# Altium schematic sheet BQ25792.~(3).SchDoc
size A2; Date: Not shown in title block; ApprovedBy: Not shown in title block; CheckedBy: Not shown in title block; Author: Not shown in title block; CompanyName: Not shown in title block; Engineer: Not shown in title block; Organization: Not shown in title block; Address1: Not shown in title block; Address2: Not shown in title block; Address3: Not shown in title block; Address4: Not shown in title block; DocumentNumber: 2; Revision: Use project parameter SCH_Rev; SheetNumber: 2; SheetTotal: 3; PageSetup: Record=PageOptions¦CenterHorizontal=True¦CenterVertical=True¦PrintScale=1.00¦XCorrection=1.00¦YCorrection=1.00¦PrintKind=0¦BorderSize=5000000¦LeftOffset=0¦BottomOffset=0¦Orientation=2¦PaperLength=1000¦PaperWidth=1000¦Scale=100¦PaperSource=15¦PrintQuality=600¦MediaType=1¦DitherType=10¦PaperKind=Letter¦PrintScaleMode=1
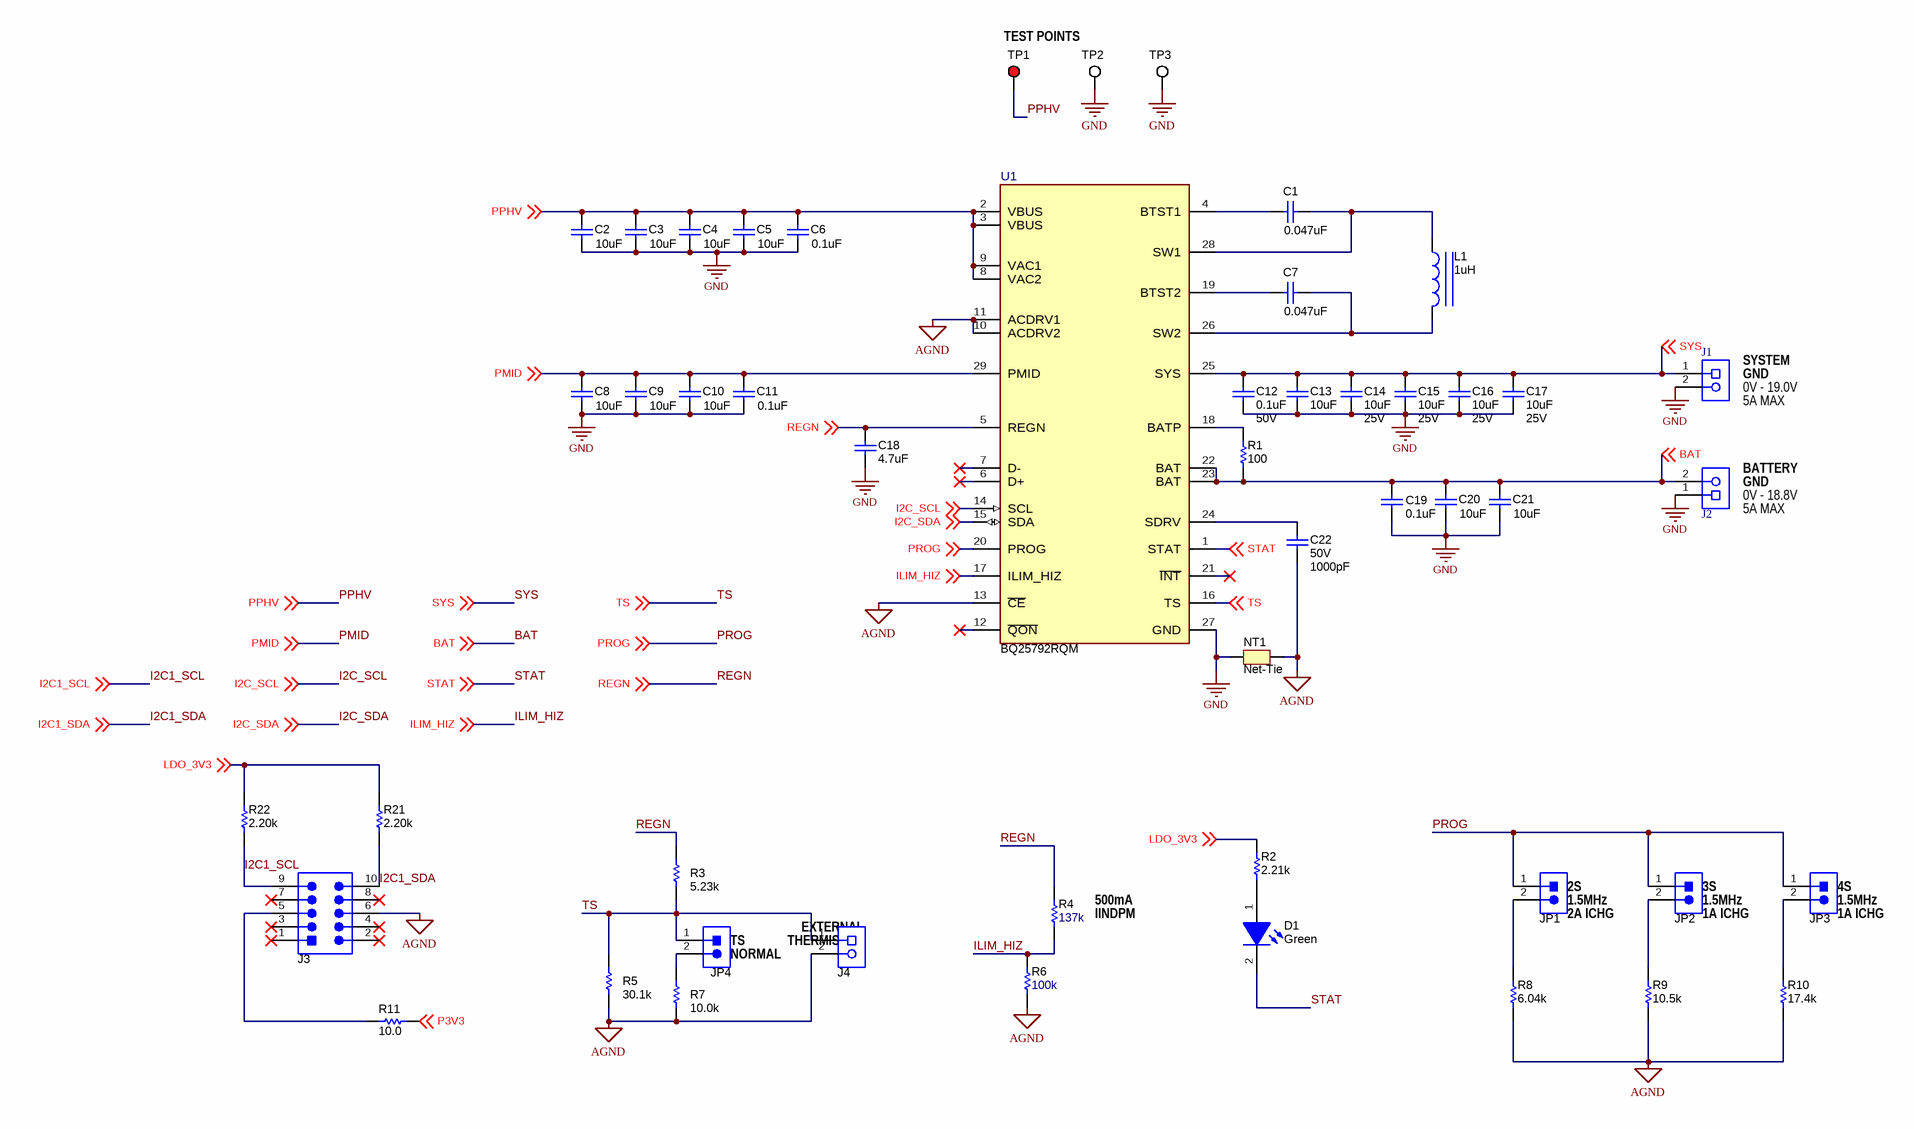
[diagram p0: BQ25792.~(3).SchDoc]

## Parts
C1  ValueDisplayed: 0.047uF  [0402]  (hidden comment: GRM155R71E473KA88D)
C2  ValueDisplayed: 10uF  [0603]  (hidden comment: GRT188R61E106ME13D)
C3  ValueDisplayed: 10uF  [0603]  (hidden comment: GRT188R61E106ME13D)
C4  ValueDisplayed: 10uF  [0603]  (hidden comment: GRT188R61E106ME13D)
C5  ValueDisplayed: 10uF  [0603]  (hidden comment: GRT188R61E106ME13D)
C6  ValueDisplayed: 0.1uF  [0402]  (hidden comment: C1005X7R1H104K050BE)
C7  ValueDisplayed: 0.047uF  [0402]  (hidden comment: GRM155R71E473KA88D)
C8  ValueDisplayed: 10uF  [0603]  (hidden comment: GRT188R61E106ME13D)
C9  ValueDisplayed: 10uF  [0603]  (hidden comment: GRT188R61E106ME13D)
C10  ValueDisplayed: 10uF  [0603]  (hidden comment: GRT188R61E106ME13D)
C11  ValueDisplayed: 0.1uF  [0402]  (hidden comment: C1005X7R1H104K050BE)
C12  ValueDisplayed: 0.1uF  VDC_V: 50V  [0402]  (hidden comment: C1005X7R1H104K050BE)
C13  ValueDisplayed: 10uF  [0805_HV]  (hidden comment: C2012X5R1E106K125AB)
C14  ValueDisplayed: 10uF  VDC_V: 25V  [0805_HV]  (hidden comment: C2012X5R1E106K125AB)
C15  ValueDisplayed: 10uF  VDC_V: 25V  [0805_HV]  (hidden comment: C2012X5R1E106K125AB)
C16  ValueDisplayed: 10uF  VDC_V: 25V  [0805_HV]  (hidden comment: C2012X5R1E106K125AB)
C17  ValueDisplayed: 10uF  VDC_V: 25V  [0805_HV]  (hidden comment: C2012X5R1E106K125AB)
C18  ValueDisplayed: 4.7uF  [0603]  (hidden comment: GRM188R61C475KAAJ)
C19  ValueDisplayed: 0.1uF  [0402L]  (hidden comment: C1005X7R1H104K050BE)
C20  ValueDisplayed: 10uF  [0603]  (hidden comment: GRT188R61E106ME13D)
C21  ValueDisplayed: 10uF  [0603]  (hidden comment: GRT188R61E106ME13D)
C22  VDC_V: 50V  ValueDisplayed: 1000pF  [0402]  (hidden comment: C0402C102K5RACTU)
D1  value Green  [LED_LTST-C190]  (hidden comment: LTST-C190GKT)
J1  ED120/2DS  [On-Shore_ED120_2DS]  (value not drawn)
J2  ED120/2DS  [On-Shore_ED120_2DS]  (value not drawn)
J3  N2510-6002-RB  [CONN_2510-6002]  (value not drawn)
J4  0393570002  [MOLEX_39357-0002]  (value not drawn)
JP1  Header_2x1  [CONN_PEC02SAAN]  (value not drawn)
JP2  Header_2x1  [CONN_PEC02SAAN]  (value not drawn)
JP3  Header_2x1  [CONN_PEC02SAAN]  (value not drawn)
JP4  Header_2x1  [CONN_PEC02SAAN]  (value not drawn)
L1  ValueDisplayed: 1uH  [IHLP-2020BZ]  (hidden comment: IHLP2020BZER1R0M11)
NT1  Net-Tie  [Net-Tie_20milWide_60milLong]  (net tie, no BOM)
R1  ValueDisplayed: 100  [0603]  (hidden comment: RC0603FR-07100RL)
R2  value 2.21k  [0402]  (hidden comment: CRCW04022K21FKED)
R3  value 5.23k  [0402]  (hidden comment: Resistor)
R4  ValueDisplayed: 137k  [0603]  (hidden comment: RC0603FR-07137KL)
R5  value 30.1k  [0402]  (hidden comment: Resistor)
R6  ValueDisplayed: 100k  [0603]  (hidden comment: RC0603FR-07100KL)
R7  value 10.0k  [0402]  (hidden comment: Resistor)
R8  ValueDisplayed: 6.04k  [0603]  (hidden comment: RC0603FR-076K04L)
R9  ValueDisplayed: 10.5k  [0603]  (hidden comment: CRCW060310K5FKEA)
R10  ValueDisplayed: 17.4k  [0603]  (hidden comment: CRCW060317K4FKEA)
R11  ValueDisplayed: 10.0  [1206]  (hidden comment: ERJ-8ENF10R0V)
R21  ValueDisplayed: 2.20k  [0201]  (hidden comment: CRCW02012K20FKED)
R22  ValueDisplayed: 2.20k  [0201]  (hidden comment: CRCW02012K20FKED)
TP1  5000  [Keystone5000]  (value not drawn)
TP2  5016  [Testpoint_Keystone_Compact]  (value not drawn)
TP3  5016  [Testpoint_Keystone_Compact]  (value not drawn)
U1  BQ25792RQM  [RQM0029A-MFG]

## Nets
AGND: C22.2 J3.6 J4.2 NT1.2 R5.1 R6.1 R7.1 R8.1 R9.1 R10.1 U1.10(ACDRV2) U1.11(ACDRV1) U1.13(~{CE})
GND: C2.1 C3.1 C4.1 C5.1 C6.2 C8.1 C9.1 C10.1 C11.2 C12.2 C13.2 C14.2 C15.2 C16.2 C17.2 C18.2 C19.2 C20.2 C21.2 J1.2 J2.1 NT1.1 TP2.1 TP3.1 U1.27(GND)
BAT: C19.1 C20.1 C21.1 J2.2 R1.1 U1.22(BAT) U1.23(BAT) ; off-sheet BAT
I2C1_SCL: J3.9 R22.1 ; off-sheet I2C1_SCL
I2C1_SDA: J3.10 R21.1 ; off-sheet I2C1_SDA
I2C_SCL: U1.14(SCL) ; off-sheet I2C_SCL
I2C_SDA: U1.15(SDA) ; off-sheet I2C_SDA
ILIM_HIZ: R4.1 R6.2 U1.17(ILIM_HIZ) ; off-sheet ILIM_HIZ
LDO_3V3: R2.2 R21.2 R22.2 ; off-sheet LDO_3V3
P3V3: R11.2 ; off-sheet P3V3
PMID: C8.2 C9.2 C10.2 C11.1 U1.29(PMID) ; off-sheet PMID
PPHV: C2.2 C3.2 C4.2 C5.2 C6.1 TP1.1 U1.2(VBUS) U1.3(VBUS) U1.8(VAC2) U1.9(VAC1) ; off-sheet PPHV
PROG: JP1.1 JP2.1 JP3.1 U1.20(PROG) ; off-sheet PROG
REGN: C18.1 R3.2 R4.2 U1.5(REGN) ; off-sheet REGN
STAT: D1.2(K) U1.1(STAT) ; off-sheet STAT
SYS: C12.1 C13.1 C14.1 C15.1 C16.1 C17.1 J1.1 U1.25(SYS) ; off-sheet SYS
TS: J4.1 JP4.1 R3.1 R5.2 U1.16(TS) ; off-sheet TS
NetC1_1: C1.1 U1.4(BTST1)
NetC1_2: C1.2 L1.1 U1.28(SW1)
NetC7_1: C7.1 U1.19(BTST2)
NetC7_2: C7.2 L1.2 U1.26(SW2)
NetC22_1: C22.1 U1.24(SDRV)
NetD1_1: D1.1(A) R2.1
NetJ3_5: J3.5 R11.1
NetJP1_2: JP1.2 R8.2
NetJP2_2: JP2.2 R9.2
NetJP3_2: JP3.2 R10.2
NetJP4_2: JP4.2 R7.2
NetR1_2: R1.2 U1.18(BATP)

Not connected (* = marked no-connect by the designer): J3 1* 2* 3* 4* 7* 8*; U1 6(D+)* 7(D-)* 12(~{QON})* 21(~{INT})*

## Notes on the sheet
- TEST POINTS
- (near J1) GND
- (near J1) 0V - 19.0V
- (near J1) 5A MAX
- (near J1) SYSTEM
- (near J2) BATTERY
- (near J2) GND
- (near J2) 0V - 18.8V
- (near J2) 5A MAX
- (near JP4) TS
- (near J4) EXTERNAL
- (near J4) THERMISTOR
- (near R4) 500mA
- (near R4) IINDPM
- (near JP1) 2S
- (near JP1) 1.5MHz
- (near JP1) 2A ICHG
- (near JP2) 3S
- (near JP2) 1.5MHz
- (near JP2) 1A ICHG
- (near JP3) 4S
- (near JP3) 1.5MHz
- (near JP3) 1A ICHG
- (near JP4) NORMAL
- (near J4) GND

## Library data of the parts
C1 C7 = CMP-0006669-2: CAP, CERM, 0.047 uF, 25 V, +/- 10%, X7R, 0402; Manufacturer: MuRata; TaMin_C: -55°C; Polarized: N; SizeAreaWB_mm2: 3; Value1: Unknown; U/M: EA; TaMax_C: 125°C; SizeZ_mm: 0.6; SizeX_mm: 1; SizeY_mm: 0.5; Value2: 25V; Cap_F: 47nF; AEC Category: Q200
C2-C5 C8-C10 C20 C21 = CMP-0007501-5: CAP, CERM, 10 uF, 25 V, +/- 20%, X5R, 0603; Manufacturer: MuRata; TaMin_C: -55°C; Polarized: N; SizeAreaWB_mm2: 4.68; Value1: Unknown; U/M: EA; Value: 10uF; TaMax_C: 85°C; SizeZ_mm: 1; SizeX_mm: 1.6; SizeY_mm: 0.8; Value2: 25V; SizeArea_mm2: 1.28; Cap_F: 10µF; AEC Category: Q200
C6 C11 = CMP-0064946-2: CAP, CERM, 0.1 uF, 50 V,+/- 10%, X7R, 0402; Manufacturer: TDK; TaMin_C: -55°C; Polarized: N; SizeAreaWB_mm2: 3; Value1: Unknown; U/M: EA; Value: 0.1uF; TaMax_C: 125°C; SizeZ_mm: 0.6; SizeX_mm: 1; SizeY_mm: 0.5; Value2: 50V; Cap_F: 100nF; AEC Category: Q200
C12 = CMP-0064946-2: CAP, CERM, 0.1 uF, 50 V,+/- 10%, X7R, 0402; Manufacturer: TDK; TaMin_C: -55°C; Polarized: N; SizeAreaWB_mm2: 3; Value1: Unknown; U/M: EA; Value: 0.1uF; TaMax_C: 125°C; SizeZ_mm: 0.6; SizeX_mm: 1; SizeY_mm: 0.5; Cap_F: 100nF; AEC Category: Q200
C13 = CMP-0007828-2: CAP, CERM, 10 uF, 25 V, +/- 10%, X5R, 0805; Manufacturer: TDK; TaMin_C: -55°C; Polarized: N; SizeAreaWB_mm2: 6.75; Value1: Unknown; U/M: EA; Value: 10uF; TaMax_C: 85°C; SizeZ_mm: 1.45; SizeX_mm: 2; SizeY_mm: 1.25; Cap_Case: 0805; Value2: 25V; SizeArea_mm2: 2.5; Cap_F: 10µF; AEC Category: Q200
C14-C17 = CMP-0007828-2: CAP, CERM, 10 uF, 25 V, +/- 10%, X5R, 0805; Manufacturer: TDK; TaMin_C: -55°C; Polarized: N; SizeAreaWB_mm2: 6.75; Value1: Unknown; U/M: EA; Value: 10uF; TaMax_C: 85°C; SizeZ_mm: 1.45; SizeX_mm: 2; SizeY_mm: 1.25; Cap_Case: 0805; SizeArea_mm2: 2.5; Cap_F: 10µF; AEC Category: Q200
C18 = CMP-0007341-5: CAP, CERM, 4.7 uF, 16 V, +/- 10%, X5R, 0603; Manufacturer: MuRata; TaMin_C: -55°C; Polarized: N; SizeAreaWB_mm2: 4.68; Value1: Unknown; U/M: EA; Value: 4.7uF; TaMax_C: 85°C; SizeZ_mm: 1; SizeX_mm: 1.6; SizeY_mm: 0.8; Value2: 16V; SizeArea_mm2: 1.28; Cap_F: 4.7µF; AEC Category: Q200
C19 = CMP-0064946-2: CAP, CERM, 0.1 uF, 50 V,+/- 10%, X7R, 0402; Manufacturer: TDK; TaMin_C: -55°C; Polarized: N; SizeAreaWB_mm2: 3; Value1: Unknown; U/M: EA; Value: 0.1uF; TaMax_C: 125°C; SizeZ_mm: 0.6; SizeX_mm: 1; SizeY_mm: 0.5; Cap_Case: 0402; Value2: 50V; Cap_F: 100nF; AEC Category: Q200
C22 = CMP-0006235-2: CAP, CERM, 1000 pF, 50 V, +/- 10%, X7R, 0402; Manufacturer: Kemet; TaMin_C: -55°C; Polarized: N; SizeAreaWB_mm2: 3; Value1: Unknown; U/M: EA; Value: 1000pF; TaMax_C: 125°C; SizeZ_mm: 0.6; SizeX_mm: 1; SizeY_mm: 0.5; Cap_F: 1nF; AEC Category: Q200
D1 = CMP-0002827-3: LED, Green, SMD; Manufacturer: Lite-On; Vf_V: 2.1V; Io_A: 20mA; Power_TotalModule: 100mW; Value1: 0.1W
J1 J2 = CMP-0074910-1: Terminal Block, 5.08 mm, 2x1, Brass, TH; Manufacturer: On-Shore Technology; Cert_VDE: Y; CNHeader: False; Current_A: 15A; Green_Lifecycle: Not Set; Shrouded: N; Gender: Female; Green_REACh: Incomplete; Voltage_V: 300V; Row_Count: 1; Pitch_mm: 5.08; CT: True
J3 = CMP-0055448-2: Header (shrouded), 100mil, 5x2, High-Temperature, Gold, TH; Manufacturer: 3M; Green_Lifecycle: Active; Green_REACh: Passed
J4 = CMP-0055341-2: Terminal Block, 3.5 mm, 2x1, Tin, TH; Manufacturer: Molex; CNHeader: FALSE; CT: TRUE; Green_Lifecycle: Not Set; Green_REACh: Incomplete
JP1-JP4 = CMP-0002337-1: Header, 100mil, 2x1, Tin, TH; PartNumber: PEC02SAAN; Manufacturer: Sullins Connector Solutions; Pitch_mm: 2.54; Gender: Male; Shrouded: N; Row_Count: 1; Current_A: 3A; Voltage_V: 1.8kV; Cert_UL: Y; CNHeader: TRUE; CT: FALSE; Green_Lifecycle: Not Set; Green_REACh: Incomplete
L1 = CMP-0063290-1: Inductor, Shielded Drum Core, Powdered Iron, 1 uH, 7 A, 0.0181 ohm, SMD; Manufacturer: Vishay-Dale; Isat: 7A @ 20% inductance drop; Irms: 7.5A @ 40C rise; Green_Lifecycle: Active; SizeAreaWB_mm2: 53.7782; DCR_ohm: 0.0181; Green_REACh: Passed; Value: 1uH; Imax_A: 7A; SizeZ_mm: 2; SizeX_mm: 5.49; SizeY_mm: 5.18; SizeArea_mm2: 28.4382; Ind_H: 1µH; AEC Category: Q200
NT1 = CMP-0078142-3: Single point connection between nets.
R1 = CMP-0022736-4: RES, 100, 1%, 0.1 W, 0603; Manufacturer: Yageo; Power_W: 100mW; TempCo: 100 ppm/C; Value_Code: 100R; Value: 100; EIA_Code: E96; SizeX_mm: 1.6; SizeY_mm: 0.8; SizeZ_mm: 1; Value2: 0.1W; SizeArea_mm2: 1.28; AEC Qualified: N; VDC_V: 75V; AEC Category: Q200; SizeAreaWB_mm2: 4.68
R2 = CMP-0026232-2: RES, 2.21 k, 1%, 0.063 W, AEC-Q200 Grade 0, 0402; Manufacturer: Vishay-Dale; Value_Code: 2k21; Power_W: 63mW; Value2: 0.063W; VDC_V: 50V; TempCo: 100 ppm/C; EIA_Code: E96; AEC Category: Q200; AEC Grade: 0; AEC Qualified: Y; SizeArea_mm2: 0.5; SizeX_mm: 1; SizeZ_mm: 0.6
R3 = CMP-0026464-2: RES, 5.23 k, 1%, 0.063 W, AEC-Q200 Grade 0, 0402; PartNumber: CRCW04025K23FKED; Manufacturer: Vishay-Dale; Value_Code: 5k23; Power_W: 63mW; Value2: 0.063W; VDC_V: 50V; TempCo: 100 ppm/C; EIA_Code: E96; AEC Category: Q200; AEC Qualified: Y; AEC Grade: 0; SizeArea_mm2: 0.5; SizeX_mm: 1; SizeZ_mm: 0.6
R4 = CMP-0022788-4: RES, 137 k, 1%, 0.1 W, 0603; Manufacturer: Yageo; Power_W: 100mW; TempCo: 100 ppm/C; Value: 137k; EIA_Code: E96; SizeX_mm: 1.6; SizeY_mm: 0.8; SizeZ_mm: 1; Value2: 0.1W; SizeArea_mm2: 1.28; AEC Qualified: N; VDC_V: 75V; AEC Category: Q200; SizeAreaWB_mm2: 4.68
R5 = CMP-0026284-2: RES, 30.1 k, 1%, 0.063 W, AEC-Q200 Grade 0, 0402; PartNumber: CRCW040230K1FKED; Manufacturer: Vishay-Dale; Value_Code: 30k1; Power_W: 63mW; Value2: 0.063W; VDC_V: 50V; TempCo: 100 ppm/C; EIA_Code: E96; AEC Category: Q200; AEC Qualified: Y; AEC Grade: 0; SizeArea_mm2: 0.5; SizeX_mm: 1; SizeZ_mm: 0.6
R6 = CMP-0022735-5: RES, 100 k, 1%, 0.1 W, 0603; Manufacturer: Yageo; Power_W: 100mW; TempCo: 100 ppm/C; Value: 100k; EIA_Code: E96; SizeX_mm: 1.6; SizeY_mm: 0.8; SizeZ_mm: 1; Value2: 0.1W; SizeArea_mm2: 1.28; AEC Qualified: N; VDC_V: 75V; AEC Category: Q200; SizeAreaWB_mm2: 4.68
R7 = CMP-0025958-3: RES, 10.0 k, 1%, 0.063 W, AEC-Q200 Grade 0, 0402; PartNumber: CRCW040210K0FKED; Manufacturer: Vishay-Dale; Res_ohm: 10k; Value_Code: 10k0; Power_W: 63mW; Value2: 0.063W; VDC_V: 50V; TempCo: 100 ppm/C; EIA_Code: E96; AEC Category: Q200; AEC Qualified: Y; AEC Grade: 0; SizeArea_mm2: 0.5; SizeX_mm: 1; SizeZ_mm: 0.6
R8 = CMP-0023246-5: RES, 6.04 k, 1%, 0.1 W, 0603; Manufacturer: Yageo; Power_W: 100mW; TempCo: 100 ppm/C; Value_Code: 6k04; Value: 6.04k; EIA_Code: E96; SizeX_mm: 1.6; SizeY_mm: 0.8; SizeZ_mm: 1; Value2: 0.1W; SizeArea_mm2: 1.28; AEC Qualified: N; VDC_V: 75V; AEC Category: Q200; SizeAreaWB_mm2: 4.68
R9 = CMP-0022000-4: RES, 10.5 k, 1%, 0.1 W, AEC-Q200 Grade 0, 0603; Manufacturer: Vishay-Dale; Power_W: 100mW; TempCo: 100 ppm/C; Value_Code: 10k5; Value: 10.5k; EIA_Code: E96; SizeX_mm: 1.6; SizeY_mm: 0.8; SizeZ_mm: 1; Value2: 0.1W; SizeArea_mm2: 1.28; AEC Qualified: Y; VDC_V: 75V; AEC Category: Q200; AEC Grade: 0
R10 = CMP-0022089-4: RES, 17.4 k, 1%, 0.1 W, AEC-Q200 Grade 0, 0603; Manufacturer: Vishay-Dale; Power_W: 100mW; TempCo: 100 ppm/C; Value_Code: 17k4; Value: 17.4k; EIA_Code: E96; SizeX_mm: 1.6; SizeY_mm: 0.8; SizeZ_mm: 1; Value2: 0.1W; SizeArea_mm2: 1.28; AEC Qualified: Y; VDC_V: 75V; AEC Category: Q200; AEC Grade: 0
R11 = CMP-0017299-3: RES, 10.0, 1%, 0.25 W, AEC-Q200 Grade 0, 1206; Manufacturer: Panasonic; Power_W: 250mW; TempCo: 100 ppm/C; Value_Code: 10R0; Value: 10.0; EIA_Code: E96; Res_ohm: 10; SizeX_mm: 3.2; SizeY_mm: 1.6; SizeZ_mm: 1.35; Value2: 0.25W; SizeArea_mm2: 5.12; AEC Qualified: Y; VDC_V: 200V; AEC Category: Q200; AEC Grade: 0; SizeAreaWB_mm2: 10.92
R21 R22 = CMP-0027272-3: RES, 2.20 k, 1%, 0.05 W, 0201; Manufacturer: Vishay-Dale; Power_W: 50mW; TempCo: 100 ppm/C; Value_Code: 2k20; Value: 2.20k; Res_ohm: 2.2k; SizeX_mm: 0.6; SizeY_mm: 0.3; SizeZ_mm: 0.26; Value2: 0.05W; SizeArea_mm2: 0.18; AEC Qualified: N; VDC_V: 30V; AEC Category: Q200
TP1 = CMP-0055137-1: Test Point, Miniature, Red, TH; Manufacturer: Keystone; CNHeader: FALSE; ContactFinish: Silver; CT: TRUE; Green_Lifecycle: Active; Green_REACh: Passed
TP2 TP3 = CMP-0055153-1: Test Point, Compact, SMT; Manufacturer: Keystone; CNHeader: FALSE; CT: TRUE; Green_Lifecycle: Active; Green_REACh: Passed
U1 = CMP-0088656-1: BQ2579x HotRod; Manufacturer: Texas Instruments; SizeZ_mm: 1mm; Standoff Height: 0mm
